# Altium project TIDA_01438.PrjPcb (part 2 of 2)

## Sheet TIDA_01438_TID_ADS1262.SchDoc
size 431 x 279 mm; Date: Not shown in title block; ApprovedBy: Not shown in title block; CheckedBy: Not shown in title block; Author: Not shown in title block; CompanyName: Not shown in title block; Engineer: Not shown in title block; Organization: Not shown in title block; Address1: Not shown in title block; Address2: Not shown in title block; Address3: Not shown in title block; Address4: Not shown in title block; DocumentNumber: 1; Revision: Use project parameter SCH_Rev; SheetNumber: 2; SheetTotal: 3; PageSetup: Record=PageOptions¦CenterHorizontal=True¦CenterVertical=True¦PrintScale=0.62¦XCorrection=1.00¦YCorrection=1.00¦PrintKind=0¦BorderSize=5000000¦LeftOffset=0¦BottomOffset=0¦Orientation=2¦PaperLength=1000¦PaperWidth=1000¦Scale=100¦PaperSource=15¦PrintQuality=-3¦MediaType=1¦DitherType=10¦PrintScaleMode=1¦PaperKind=11x17¦PaperIndex=3
Used 2 times, as channels CH1/ADC, CH2/ADC. Parts and nets are listed once, with the designators drawn on the sheet.
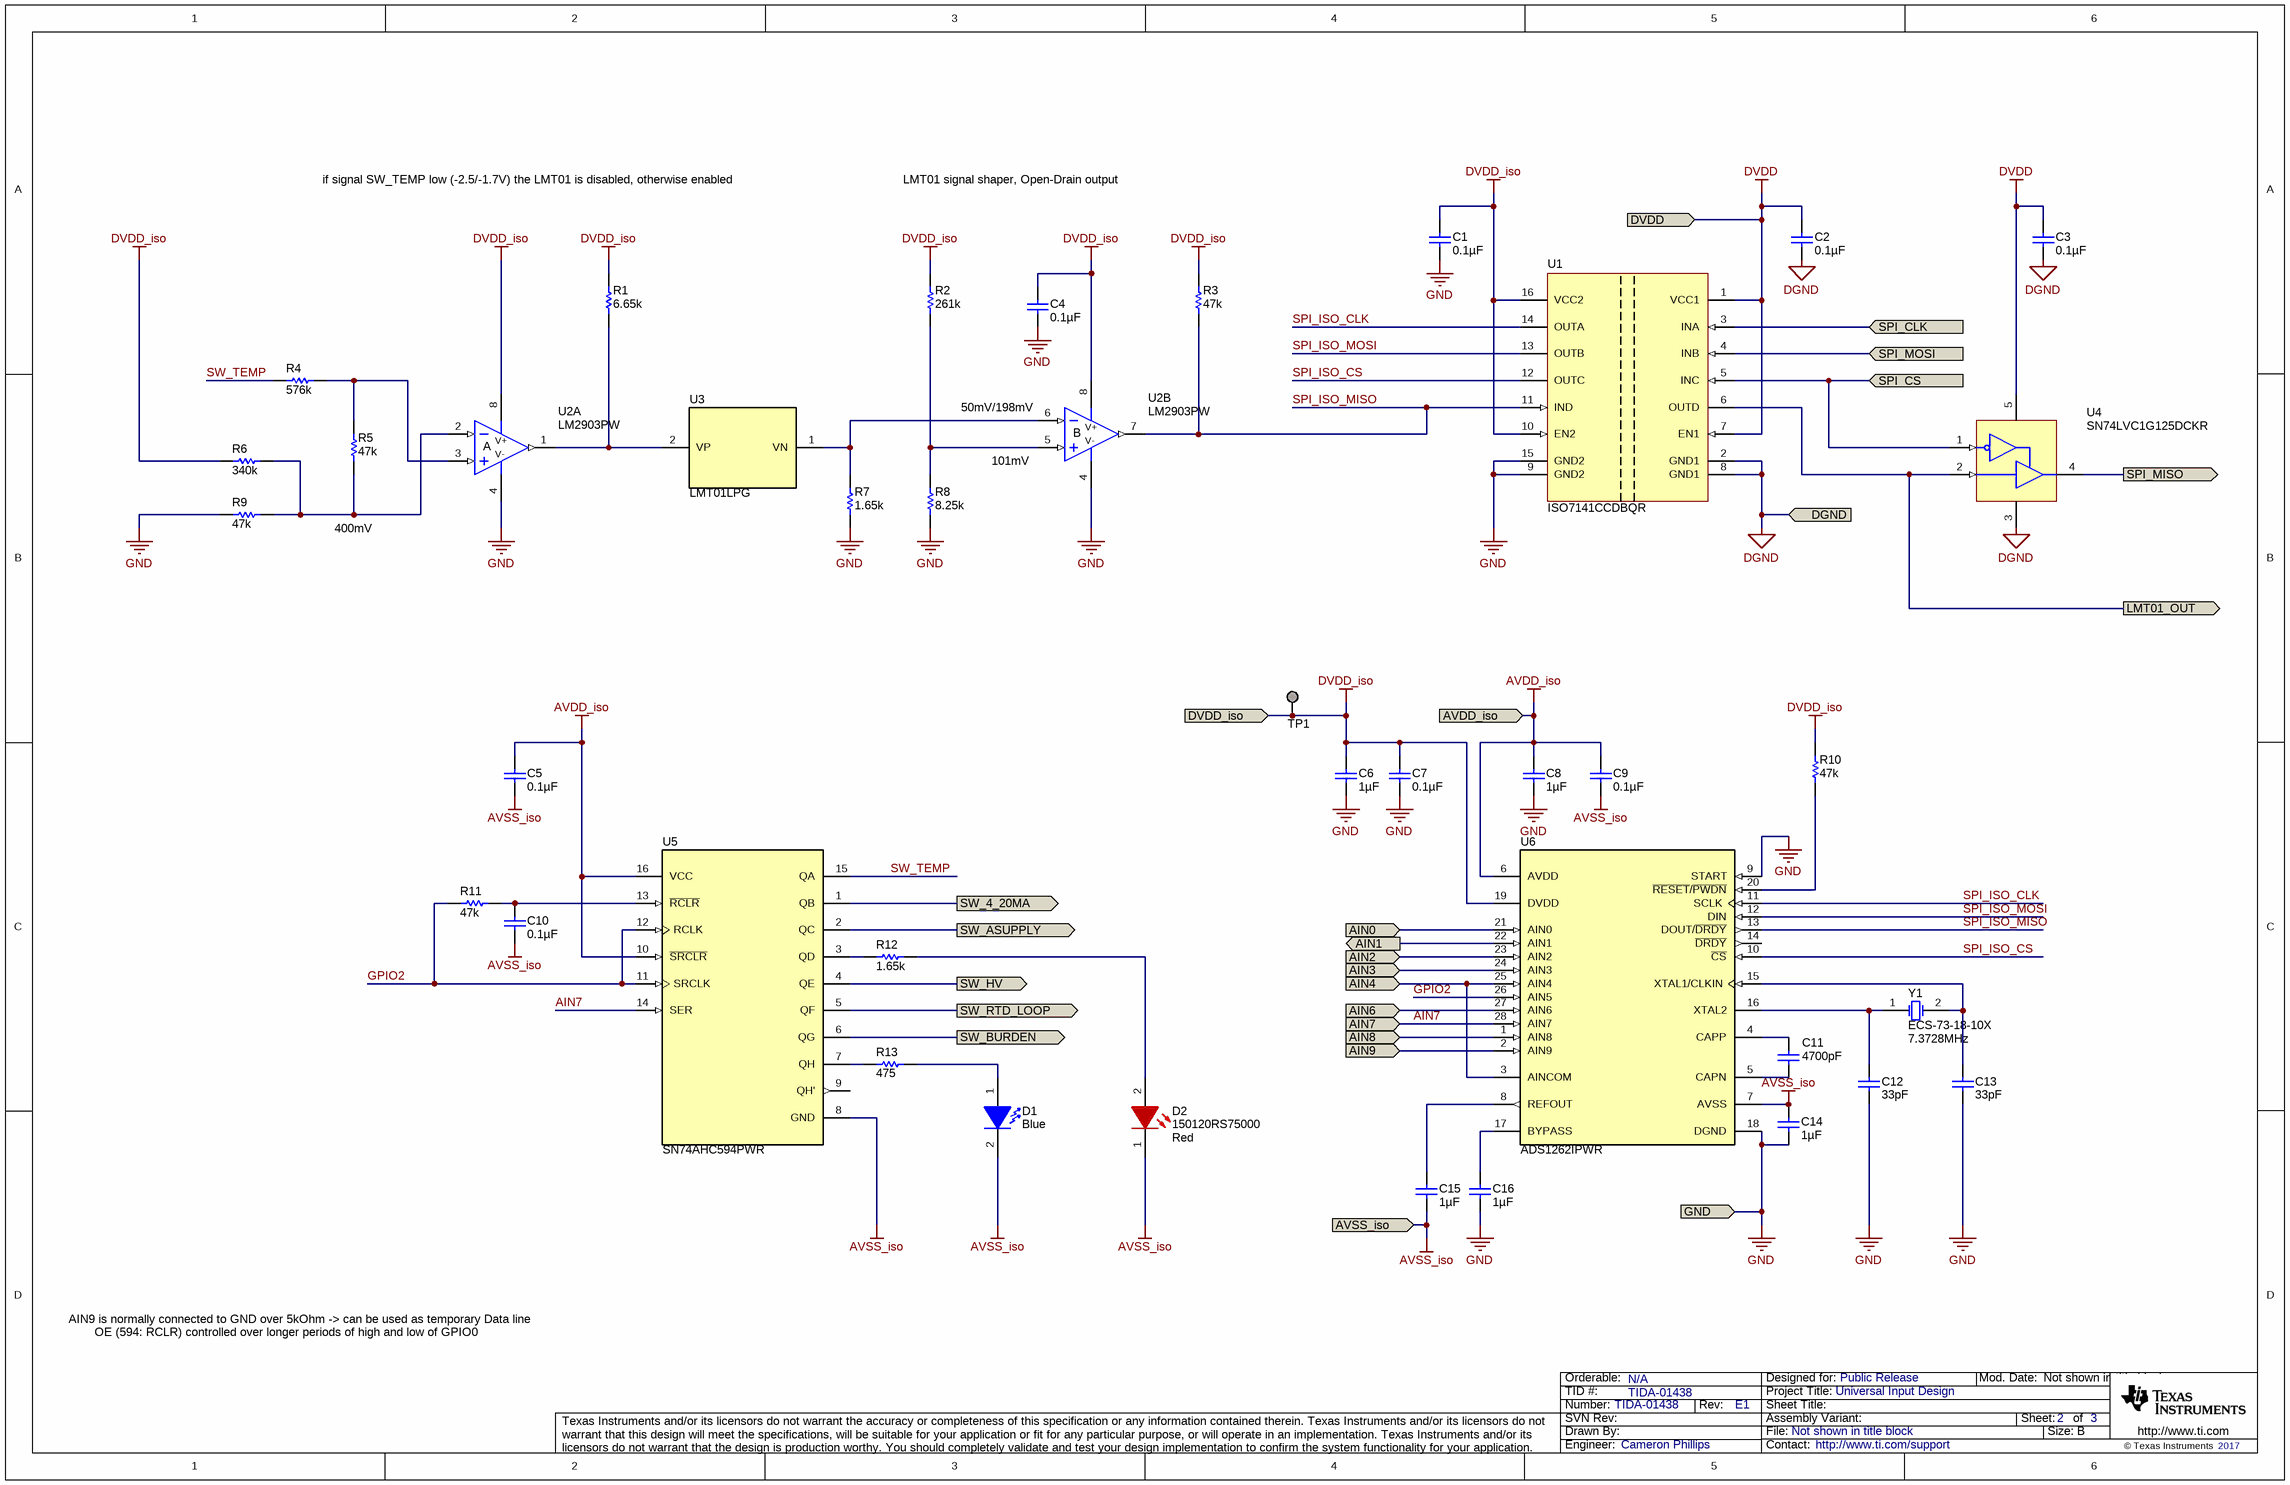
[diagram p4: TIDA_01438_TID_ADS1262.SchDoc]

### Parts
C1  ValueDisplayed: 0.1µF  [0402]  (hidden comment: C1005X7R1H104K)
C2  ValueDisplayed: 0.1µF  [0402]  (hidden comment: C1005X7R1H104K)
C3  ValueDisplayed: 0.1µF  [0402]  (hidden comment: C1005X7R1H104K)
C4  ValueDisplayed: 0.1µF  [0402]  (hidden comment: C1005X7R1H104K)
C5  ValueDisplayed: 0.1µF  [0402]  (hidden comment: C1005X7R1H104K)
C6  ValueDisplayed: 1µF  [0603]  (hidden comment: C1608X7R1C105K)
C7  ValueDisplayed: 0.1µF  [0402]  (hidden comment: C1005X7R1H104K)
C8  ValueDisplayed: 1µF  [0603]  (hidden comment: C1608X7R1C105K)
C9  ValueDisplayed: 0.1µF  [0402]  (hidden comment: C1005X7R1H104K)
C10  ValueDisplayed: 0.1µF  [0402]  (hidden comment: C1005X7R1H104K)
C11  ValueDisplayed: 4700pF  [0603]  (hidden comment: C1608C0G1E472J)
C12  ValueDisplayed: 33pF  [0402]  (hidden comment: GRM1555C1E330JA01D)
C13  ValueDisplayed: 33pF  [0402]  (hidden comment: GRM1555C1E330JA01D)
C14  ValueDisplayed: 1µF  [0603]  (hidden comment: C1608X7R1C105K)
C15  ValueDisplayed: 1µF  [0603]  (hidden comment: C1608X7R1C105K)
C16  ValueDisplayed: 1µF  [0603]  (hidden comment: C1608X7R1C105K)
D1  value Blue  [LB Q39G_BLUE]  (hidden comment: LB Q39G-L2N2-35-1)
D2  150120RS75000  value Red  [WL_SMCW_RED_1206]
R1  ValueDisplayed: 6.65k  [0402]  (hidden comment: CRCW04026K65FKED)
R2  ValueDisplayed: 261k  [0402]  (hidden comment: CRCW0402261KFKED)
R3  ValueDisplayed: 47k  [0402]  (hidden comment: CRCW040247K0JNED)
R4  ValueDisplayed: 576k  [0402]  (hidden comment: CRCW0402576KFKED)
R5  ValueDisplayed: 47k  [0402]  (hidden comment: CRCW040247K0JNED)
R6  ValueDisplayed: 340k  [0402]  (hidden comment: CRCW0402340KFKED)
R7  ValueDisplayed: 1.65k  [0402]  (hidden comment: CRCW04021K65FKED)
R8  ValueDisplayed: 8.25k  [0402]  (hidden comment: CRCW04028K25FKED)
R9  ValueDisplayed: 47k  [0402]  (hidden comment: CRCW040247K0JNED)
R10  ValueDisplayed: 47k  [0402]  (hidden comment: CRCW040247K0JNED)
R11  ValueDisplayed: 47k  [0402]  (hidden comment: CRCW040247K0JNED)
R12  ValueDisplayed: 1.65k  [0402]  (hidden comment: CRCW04021K65FKED)
R13  ValueDisplayed: 475  [0402]  (hidden comment: CRCW0402475RFKED)
TP1  TESTPOINT  [TESTPOINT]  (value not drawn)  (no BOM)
U1  ISO7141CCDBQR  [DBQ0016A_N]
U2  LM2903PW  [PW0008A_N]  (parts A,B of 2)
U3  LMT01LPG  [LPG0002A]
U4  SN74LVC1G125DCKR  [DCK0005A_N]
U5  SN74AHC594PWR  [PW0016A_N]
U6  ADS1262IPWR  [PW0028A_N]
Y1  ECS-73-18-10X  Frequency: 7.3728MHz  [ECS-3x10X]

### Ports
AIN0 (in), AIN1 (out), AIN2 (in), AIN3 (in), AIN4 (in), AIN6 (in), AIN7 (in), AIN8 (in), AIN9 (in), AVDD_iso (in), AVSS_iso (in), DGND (in), DVDD (in), DVDD_iso (in), GND (in), LMT01_OUT (out), SPI_CLK (in), SPI_CS (in), SPI_MISO (out), SPI_MOSI (in), SW_4_20MA (out), SW_ASUPPLY (out), SW_BURDEN (out), SW_HV (out), SW_RTD_LOOP (out)

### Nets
AVDD_iso: C5.1 C8.1 C9.1 U5.10(~{SRCLR}) U5.16(VCC) U6.6(AVDD) ; port AVDD_iso
AVSS_iso: C5.2 C9.2 C10.2 C14.1 C15.2 D1.2(K) D2.1(K) U5.8(GND) U6.7(AVSS) ; port AVSS_iso
DGND: C2.2 C3.2 U1.2(GND1) U1.8(GND1) U4.3(GND) ; port DGND
DVDD: C2.1 C3.1 U1.1(VCC1) U1.7(EN1) U4.5(VCC) ; port DVDD
DVDD_iso: C1.1 C4.1 C6.1 C7.1 R1.1 R2.1 R3.1 R6.2 R10.1 TP1.1 U1.10(EN2) U1.16(VCC2) U2.8(V+) U6.19(DVDD) ; port DVDD_iso
GND: C1.2 C4.2 C6.2 C7.2 C8.2 C12.2 C13.2 C14.2 C16.2 R7.1 R8.2 R9.1 U1.9(GND2) U1.15(GND2) U2.4(V-) U6.9(START) U6.18(DGND) ; port GND
AIN0: U6.21(AIN0) ; port AIN0
AIN1: U6.22(AIN1) ; port AIN1
AIN2: U6.23(AIN2) ; port AIN2
AIN3: U6.24(AIN3) ; port AIN3
AIN4: U6.3(AINCOM) U6.25(AIN4) ; port AIN4
AIN6: U6.27(AIN6) ; port AIN6
AIN7: U5.14(SER) U6.28(AIN7) ; port AIN7
AIN8: U6.1(AIN8) ; port AIN8
AIN9: U6.2(AIN9) ; port AIN9
GPIO2: R11.1 U5.11(SRCLK) U5.12(RCLK) U6.26(AIN5)
LMT01_OUT: U1.6(OUTD) U4.2(A) ; port LMT01_OUT
SPI_CLK: U1.3(INA) ; port SPI_CLK
SPI_CS: U1.5(INC) U4.1(~{OE}) ; port SPI_CS
SPI_ISO_CLK: U1.14(OUTA) U6.11(SCLK)
SPI_ISO_CS: U1.12(OUTC) U6.10(~{CS})
SPI_ISO_MISO: R3.2 U1.11(IND) U2.7(OUT) U6.13(DOUT/~{DRDY})
SPI_ISO_MOSI: U1.13(OUTB) U6.12(DIN)
SPI_MISO: U4.4(Y) ; port SPI_MISO
SPI_MOSI: U1.4(INB) ; port SPI_MOSI
SW_4_20MA: U5.1(QB) ; port SW_4_20MA
SW_ASUPPLY: U5.2(QC) ; port SW_ASUPPLY
SW_BURDEN: U5.6(QG) ; port SW_BURDEN
SW_HV: U5.4(QE) ; port SW_HV
SW_RTD_LOOP: U5.5(QF) ; port SW_RTD_LOOP
SW_TEMP: R4.2 U5.15(QA)
NetC10_1: C10.1 R11.2 U5.13(~{RCLR})
NetC11_1: C11.1 U6.4(CAPP)
NetC11_2: C11.2 U6.5(CAPN)
NetC12_1: C12.1 U6.16(XTAL2) Y1.1(OSC1)
NetC13_1: C13.1 U6.15(XTAL1/CLKIN) Y1.2(OSC2)
NetC15_1: C15.1 U6.8(REFOUT)
NetC16_1: C16.1 U6.17(BYPASS)
NetD1_1: D1.1(A) R13.2
NetD2_2: D2.2(A) R12.2
NetR1_2: R1.2 U2.1(OUT) U3.2(VP)
NetR2_2: R2.2 R8.1 U2.5(IN+)
NetR4_1: R4.1 R5.1 U2.3(IN+)
NetR5_2: R5.2 R6.1 R9.2 U2.2(IN-)
NetR7_2: R7.2 U2.6(IN-) U3.1(VN)
NetR10_2: R10.2 U6.20(~{RESET}/~{PWDN})
NetR12_1: R12.1 U5.3(QD)
NetR13_1: R13.1 U5.7(QH)

Not connected (* = marked no-connect by the designer): U5 9(QH'); U6 14(~{DRDY})

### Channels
CH1/ADC: designators end in _ADC1; ports AIN0=AIN0 AIN1=AIN1 AIN2=AIN2 AIN3=AIN3 AIN4=AIN4 AIN6=AIN6 AIN7=AIN7 AIN8=AIN8 AIN9=AIN9 AVDD_iso=AVDD_iso AVSS_iso=AVSS_iso DGND=DGND DVDD=DVDD DVDD_iso=DVDD_iso GND=GND LMT01_OUT=LMT01_OUT1 SPI_CLK=SPI_CLK SPI_CS=SPI_CS1 SPI_MISO=SPI_MISO SPI_MOSI=SPI_MOSI SW_4_20MA=SW_4_20MA SW_ASUPPLY=SW_ASUPPLY SW_BURDEN=SW_BURDEN SW_HV=SW_HV SW_RTD_LOOP=SW_RTD_LOOP
CH2/ADC: designators end in _ADC2; ports AIN0=AIN0 AIN1=AIN1 AIN2=AIN2 AIN3=AIN3 AIN4=AIN4 AIN6=AIN6 AIN7=AIN7 AIN8=AIN8 AIN9=AIN9 AVDD_iso=AVDD_iso AVSS_iso=AVSS_iso DGND=DGND DVDD=DVDD DVDD_iso=DVDD_iso GND=GND LMT01_OUT=LMT01_OUT2 SPI_CLK=SPI_CLK SPI_CS=SPI_CS2 SPI_MISO=SPI_MISO SPI_MOSI=SPI_MOSI SW_4_20MA=SW_4_20MA SW_ASUPPLY=SW_ASUPPLY SW_BURDEN=SW_BURDEN SW_HV=SW_HV SW_RTD_LOOP=SW_RTD_LOOP

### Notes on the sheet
- if signal SW_TEMP low (-2.5/-1.7V) the LMT01 is disabled, otherwise enabled
- LMT01 signal shaper, Open-Drain output
- (near U2) 50mV/198mV
- (near U2) 101mV
- 400mV
- OE (594: RCLR) controlled over longer periods of high and low of GPIO0
- AIN9 is normally connected to GND over 5kOhm -> can be used as temporary Data line

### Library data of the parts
C1-C5 C7 C9 C10 = C1005X7R1H104K: CAP, CERM, 0.1 µF, 50 V, +/- 10%, X7R, 0402; Manufacturer: TDK; Polarized: N; CompType: Capacitor; Value: 0.1uF; U/M: EA; Cap_F: 0.0000001; Tolerance_%: 10; Value1: Unknown; VDC_V: 50; Value2: 50V; TaMin_C: -55; TaMax_C: 125; AEC Category: Q200
C6 C8 C15 C16 = C1608X7R1C105K: CAP, CERM, 1 µF, 16 V, +/- 10%, X7R, 0603; Manufacturer: TDK; Polarized: N; CompType: Capacitor; Value: 1uF; U/M: EA; Cap_F: 0.000001; Tolerance_%: 10; ESR_ohm: 0.0057; Value1: 0.0057 ohm; VDC_V: 16; Value2: 16V; TaMin_C: -55; TaMax_C: 125
C11 = C1608C0G1E472J: CAP, CERM, 4700 pF, 25 V, +/- 5%, C0G/NP0, 0603; Manufacturer: TDK; Polarized: N; CompType: Capacitor; Value: 4700pF; U/M: EA; Cap_F: 0.0000000047; Tolerance_%: 5; Value1: Unknown; VDC_V: 25; Value2: 25V; TaMin_C: -55; TaMax_C: 125
C12 C13 = GRM1555C1E330JA01D: CAP, CERM, 33 pF, 25 V, +/- 5%, C0G/NP0, 0402; Manufacturer: MuRata; Polarized: N; CompType: Capacitor; Value: 33pF; U/M: EA; Cap_F: 0.000000000033; Tolerance_%: 5; Value1: Unknown; VDC_V: 25; Value2: 25V; TaMin_C: -55; TaMax_C: 125; AEC Category: Q200
C14 = C1608X7R1C105K: CAP, CERM, 1 µF, 16 V, +/- 10%, X7R, 0603; Manufacturer: TDK; Polarized: N; CompType: Capacitor; Value: 1uF; U/M: EA; Cap_F: 0.000001; Tolerance_%: 10; ESR_ohm: 0.0057; Value1: 0.0057 ohm; VDC_V: 16; Value2: 16V; TaMin_C: -55; TaMax_C: 125; AEC Category: Q200
D1 = LB Q39G-L2N2-35-1: LED, Blue, SMD; Manufacturer: OSRAM; Vf_V: 2.85; Value2: 2.85V; Io_A: 0.15; Tjmax_C: 95; Value1: W; U/M: EA
D2 = 150120RS75000: LED, Red, SMD; Manufacturer: Wurth Elektronik; SymbolCreator: Altium; Type: AlInGaP; Vf_V: 2; Value2: 2V; Io_A: 0.02; Vr_V: 5; Ir_A: 1e-005; Tjmax_C: 85; Power_TotalModule: 0.072; Value1: 0.072W; Angle: 140; U/M: EA
R1 = CRCW04026K65FKED: RES, 6.65 k, 1%, 0.063 W, 0402; Manufacturer: Vishay-Dale; CompType: Resistor; Value: 6.65k; Res_ohm: 6650; Value_Code: 6k65; Tolerance_%: 1; Power_W: 0.063; Value2: 0.063W; VDC_V: 50; TempCo: 100 ppm/C; EIA_Code: E96; U/M: EA; AEC Category: Q200
R2 = CRCW0402261KFKED: RES, 261 k, 1%, 0.063 W, 0402; Manufacturer: Vishay-Dale; CompType: Resistor; Value: 261k; Res_ohm: 261000; Tolerance_%: 1; Power_W: 0.063; Value2: 0.063W; VDC_V: 50; TempCo: 100 ppm/C; EIA_Code: E96; U/M: EA; AEC Category: Q200
R3 R5 R9-R11 = CRCW040247K0JNED: RES, 47 k, 5%, 0.063 W, 0402; Manufacturer: Vishay-Dale; CompType: Resistor; Value: 47k; Res_ohm: 47000; Value_Code: 47k0; Tolerance_%: 5; Power_W: 0.063; Value2: 0.063W; VDC_V: 50; TempCo: 200 ppm/C; EIA_Code: E24; U/M: EA; AEC Category: Q200
R4 = CRCW0402576KFKED: RES, 576 k, 1%, 0.063 W, 0402; Manufacturer: Vishay-Dale; CompType: Resistor; Value: 576k; Res_ohm: 576000; Tolerance_%: 1; Power_W: 0.063; Value2: 0.063W; VDC_V: 50; TempCo: 100 ppm/C; EIA_Code: E96; U/M: EA; AEC Category: Q200
R6 = CRCW0402340KFKED: RES, 340 k, 1%, 0.063 W, 0402; Manufacturer: Vishay-Dale; CompType: Resistor; Value: 340k; Res_ohm: 340000; Tolerance_%: 1; Power_W: 0.063; Value2: 0.063W; VDC_V: 50; TempCo: 100 ppm/C; EIA_Code: E96; U/M: EA; AEC Category: Q200
R7 R12 = CRCW04021K65FKED: RES, 1.65 k, 1%, 0.063 W, 0402; Manufacturer: Vishay-Dale; CompType: Resistor; Value: 1.65k; Res_ohm: 1650; Value_Code: 1k65; Tolerance_%: 1; Power_W: 0.063; Value2: 0.063W; VDC_V: 50; TempCo: 100 ppm/C; EIA_Code: E96; U/M: EA; AEC Category: Q200
R8 = CRCW04028K25FKED: RES, 8.25 k, 1%, 0.063 W, 0402; Manufacturer: Vishay-Dale; CompType: Resistor; Value: 8.25k; Res_ohm: 8250; Value_Code: 8k25; Tolerance_%: 1; Power_W: 0.063; Value2: 0.063W; VDC_V: 50; TempCo: 100 ppm/C; EIA_Code: E96; U/M: EA; AEC Category: Q200
R13 = CRCW0402475RFKED: RES, 475, 1%, 0.063 W, 0402; Manufacturer: Vishay-Dale; CompType: Resistor; Value: 475; Value_Code: 475R; Tolerance_%: 1; Power_W: 0.063; Value2: 0.063W; VDC_V: 50; TempCo: 100 ppm/C; EIA_Code: E96; U/M: EA; AEC Category: Q200
TP1 = TESTPOINT: TEST POINT.  No entry in BOM.
U1 = ISO7141CCDBQR: 4242-VPK Small-Footprint and Low-Power Quad Channels Digital Isolators, DBQ0016A; Manufacturer: Texas Instruments; SymbolCreator: a0799628; CompType: IC; U/M: EA
U2 = LM2903PW: Dual Comparator, PW0008A; Manufacturer: Texas Instruments; CompType: OpAmp IC
U3 = LMT01LPG: 0.5°C Accurate 2-Pin Digital NTC or PTC Thermistor Replacement, LPG0002A; Manufacturer: Texas Instruments; SymbolCreator: Altium; CompType: IC; U/M: EA
U4 = SN74LVC1G125DCKR: Single Bus Buffer Gate With 3-State Output, DCK0005A; Alternate PartNumber: SN74LVC1G125DCKT; Manufacturer: Texas Instruments; SymbolCreator: Altium; CompType: IC; U/M: EA
U5 = SN74AHC594PWR: 8-Bit Shift Register With Output Registers, PW0016A; Manufacturer: Texas Instruments; SymbolCreator: Altium; CompType: IC; U/M: EA
U6 = ADS1262IPWR: 32-Bit, Precision, 38-kSPS, Analog-to-Digital Converter (ADC) with Programmable Gain Amplifier (PGA) and Voltage Reference, PW0028A; Manufacturer: Texas Instruments; SymbolCreator: Altium; CompType: IC; U/M: EA
Y1 = ECS-73-18-10X: Crystal, 7.3728MHz, 18pF, SMD; Manufacturer: ECS Inc.; SymbolCreator: a0412235; U/M: EA; TaMin_C: -10; TaMax_C: 60; Frequency Stability: ±50ppm

## Sheet TIDA_01438_TID_HART.SchDoc
size 431 x 279 mm; Date: Not shown in title block; ApprovedBy: Not shown in title block; CheckedBy: Not shown in title block; Author: Not shown in title block; CompanyName: Not shown in title block; Engineer: Not shown in title block; Organization: Not shown in title block; Address1: Not shown in title block; Address2: Not shown in title block; Address3: Not shown in title block; Address4: Not shown in title block; DocumentNumber: 1; Revision: Use project parameter SCH_Rev; SheetNumber: 2; SheetTotal: 3; PageSetup: Record=PageOptions¦CenterHorizontal=True¦CenterVertical=True¦PrintScale=1.00¦XCorrection=1.00¦YCorrection=1.00¦PrintKind=0¦BorderSize=5000000¦LeftOffset=0¦BottomOffset=0¦Orientation=2¦PaperLength=1000¦PaperWidth=1000¦Scale=100¦PaperSource=15¦PrintQuality=600¦MediaType=1¦DitherType=10¦PaperKind=Letter¦PrintScaleMode=1
Used 2 times, as channels CH1/HART, CH2/HART. Parts and nets are listed once, with the designators drawn on the sheet.
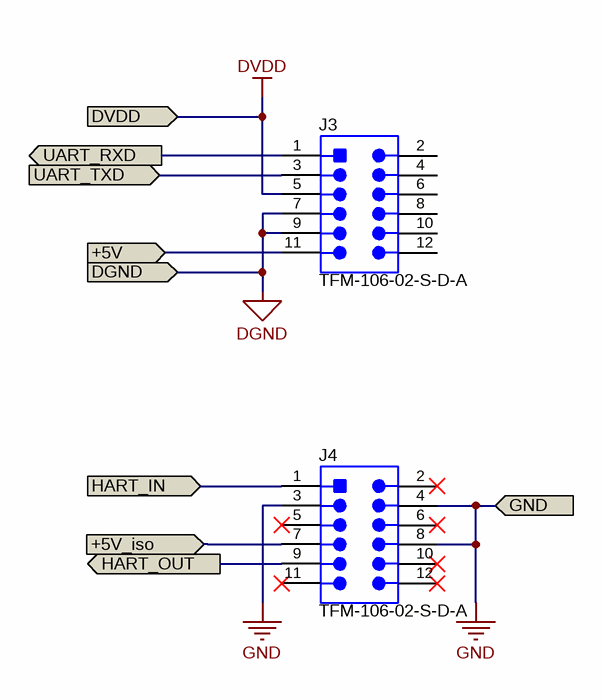
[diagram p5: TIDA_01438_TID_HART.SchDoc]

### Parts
J3  TFM-106-02-S-D-A  [Samtec_TFM-106-02-x-D-A]
J4  TFM-106-02-S-D-A  [Samtec_TFM-106-02-x-D-A]

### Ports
+5V (in), +5V_iso (in), DGND (in), DVDD (in), GND (in), HART_IN (in), HART_OUT (out), UART_RXD (out), UART_TXD (in)

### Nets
DGND: J3.7 J3.9 ; port DGND
DVDD: J3.5 ; port DVDD
GND: J4.3 J4.4 J4.8 ; port GND
+5V: J3.11 ; port +5V
+5V_iso: J4.7 ; port +5V_iso
HART_IN: J4.1 ; port HART_IN
HART_OUT: J4.9 ; port HART_OUT
UART_RXD: J3.1 ; port UART_RXD
UART_TXD: J3.3 ; port UART_TXD

Not connected (* = marked no-connect by the designer): J3 2 4 6 8 10 12; J4 2* 5* 6* 10* 11* 12*

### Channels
CH1/HART: designators end in _HART1; ports +5V=+5V +5V_iso=+5V_iso DGND=DGND DVDD=DVDD GND=GND HART_IN=HART_IN HART_OUT=HART_OUT UART_RXD=UART_RXD1 UART_TXD=UART_TXD1
CH2/HART: designators end in _HART2; ports +5V=+5V +5V_iso=+5V_iso DGND=DGND DVDD=DVDD GND=GND HART_IN=HART_IN HART_OUT=HART_OUT UART_RXD=UART_RXD2 UART_TXD=UART_TXD2

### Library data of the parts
J3 J4 = TFM-106-02-S-D-A: Header(Shrouded), 1.27mm, 6x2, Tin, SMT; Manufacturer: Samtec; SymbolCreator: a0412235; U/M: EA

## Sheet TIDA_01438_CoverSheet.SchDoc: Block Diagram
size 431 x 279 mm; Date: Not shown in title block; ApprovedBy: Not shown in title block; CheckedBy: Not shown in title block; Author: Not shown in title block; CompanyName: Not shown in title block; DrawnBy: Lars Lotzenburger; Engineer: Not shown in title block; Organization: Not shown in title block; Address1: Not shown in title block; Address2: Not shown in title block; Address3: Not shown in title block; Address4: Not shown in title block; DocumentNumber: 1; Revision: Use project parameter SCH_Rev; SheetNumber: 1; SheetTotal: 3; PageSetup: Record=PageOptions¦CenterHorizontal=True¦CenterVertical=True¦PrintScale=1.00¦XCorrection=1.00¦YCorrection=1.00¦PrintKind=0¦BorderSize=5000000¦LeftOffset=0¦BottomOffset=0¦Orientation=2¦PaperLength=1000¦PaperWidth=1000¦Scale=100¦PaperSource=15¦PrintQuality=600¦MediaType=1¦DitherType=10¦PaperKind=Letter¦PrintScaleMode=1
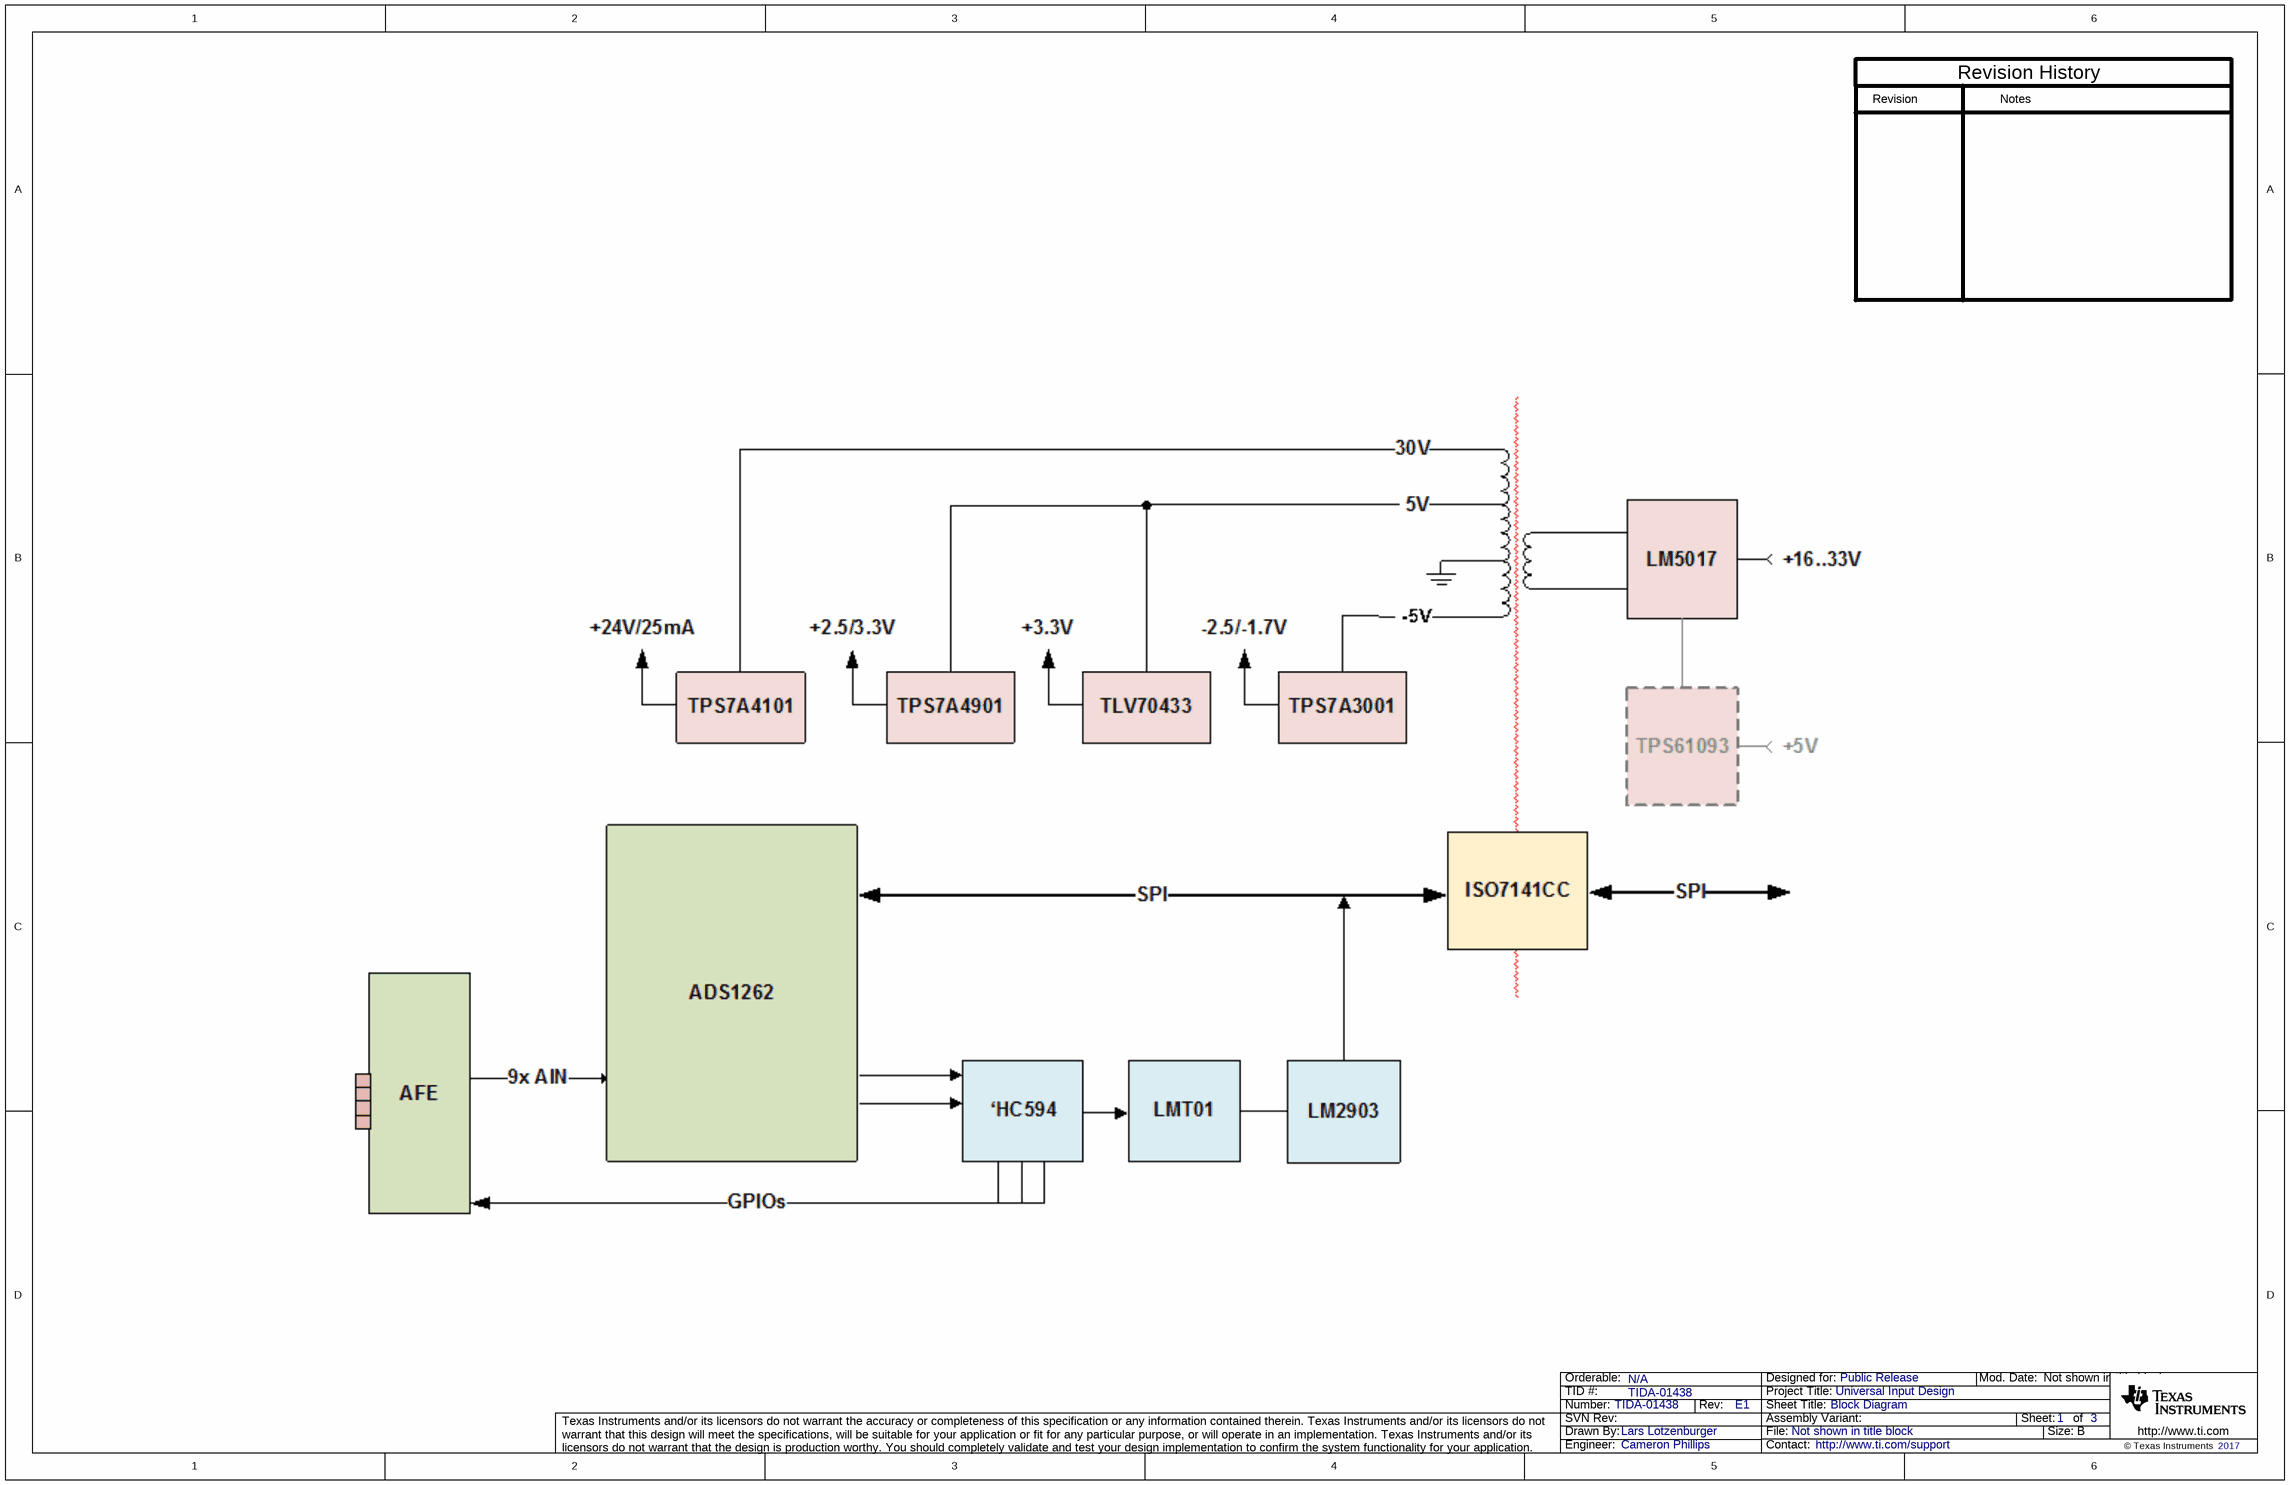
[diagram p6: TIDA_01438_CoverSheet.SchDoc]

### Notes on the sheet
- Revision
- Notes
- Revision History

## Sheet TIDA_01438_TID_Hardware.SchDoc: Hardware
size 431 x 279 mm; Date: Not shown in title block; ApprovedBy: Not shown in title block; CheckedBy: Not shown in title block; Author: Not shown in title block; CompanyName: Not shown in title block; DrawnBy: Lars Lotzenburger; Engineer: Not shown in title block; Organization: Not shown in title block; Address1: Not shown in title block; Address2: Not shown in title block; Address3: Not shown in title block; Address4: Not shown in title block; DocumentNumber: 3; Revision: Use project parameter SCH_Rev; SheetNumber: 3; SheetTotal: 3; PageSetup: Record=PageOptions¦CenterHorizontal=True¦CenterVertical=True¦PrintScale=1.00¦XCorrection=1.00¦YCorrection=1.00¦PrintKind=0¦BorderSize=5000000¦LeftOffset=0¦BottomOffset=0¦Orientation=2¦PaperLength=1000¦PaperWidth=1000¦Scale=100¦PaperSource=15¦PrintQuality=600¦MediaType=1¦DitherType=10¦PaperKind=Letter¦PrintScaleMode=1
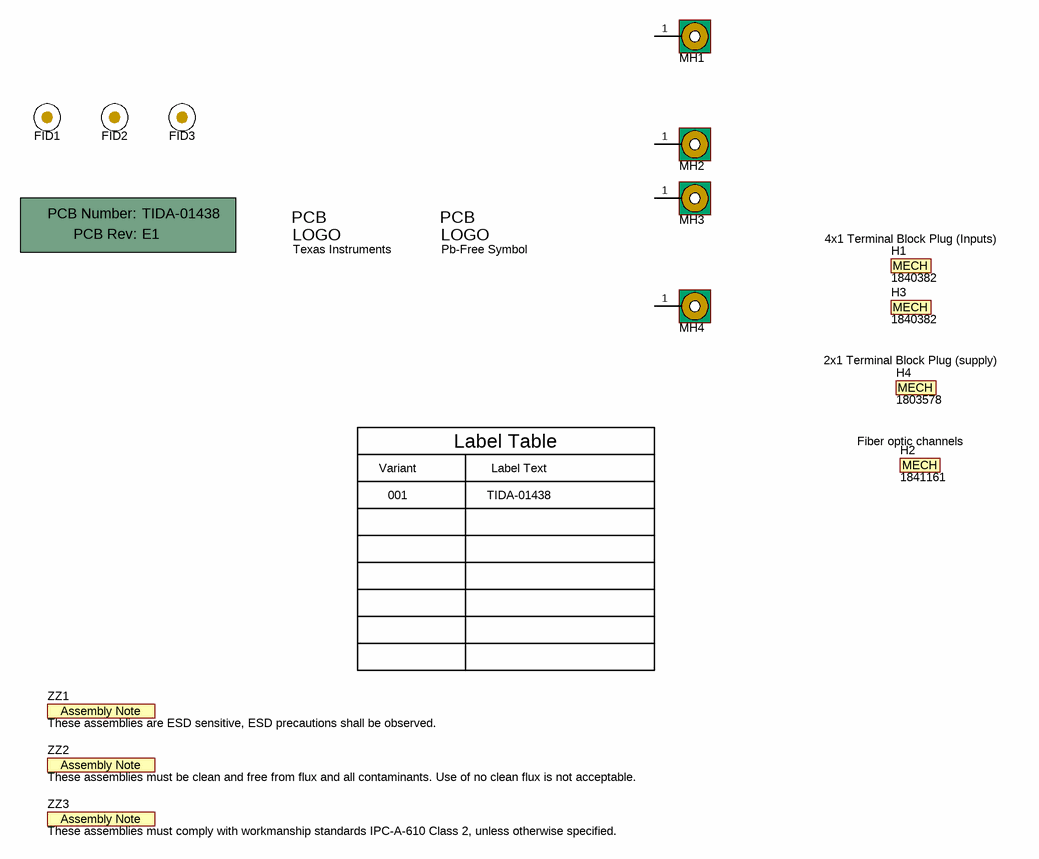
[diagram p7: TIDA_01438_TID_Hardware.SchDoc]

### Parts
!PCB1  Printed Circuit Board  (value not drawn)  (mechanical)
FID1  Fiducial  [Fiducial10-20]  (value not drawn)
FID2  Fiducial  [Fiducial10-20]  (value not drawn)
FID3  Fiducial  [Fiducial10-20]  (value not drawn)
H1  1840382  (mechanical)
H2  1841161  (mechanical)
H3  1840382  (mechanical)
H4  1803578  (mechanical)
Logo1  Texas Instruments  [TI_Stacked_SolderMask_Small]  (no BOM)
Logo2  Pb-Free Symbol  [Pb-Free_Overlay_Small]  (no BOM)
MH1  MTG_Pads  [MTGP_4-40_PanHead]  (value not drawn)  (no BOM)
MH2  MTG_Pads  [MTGP_4-40_PanHead]  (value not drawn)  (no BOM)
MH3  MTG_Pads  [MTGP_4-40_PanHead]  (value not drawn)  (no BOM)
MH4  MTG_Pads  [MTGP_4-40_PanHead]  (value not drawn)  (no BOM)
ZZ1  These assemblies are ESD sensitive, ESD precautions shall be observed.  [AssemblyNote]  (no BOM)
ZZ2  These assemblies must be clean and free from flux and all contaminants. Use of no clean flux is not acceptable.  [AssemblyNote]  (no BOM)
ZZ3  These assemblies must comply with workmanship standards IPC-A-610 Class 2, unless otherwise specified.  [AssemblyNote]  (no BOM)

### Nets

Not connected (* = marked no-connect by the designer): MH1 1; MH2 1; MH3 1; MH4 1

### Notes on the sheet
- (near H1) 4x1 Terminal Block Plug (Inputs)
- (near H4) 2x1 Terminal Block Plug (supply)
- Variant
- Label Table
- Label Text
- (near H2) Fiber optic channels
- 001
- TIDA-01438

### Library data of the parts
!PCB1 = PCB: Manufacturer: Any; PartNumber: TIDA-01438; SymbolCreator: a0412235
FID1-FID3 = Fiducial: Fiducial mark.  There is nothing to buy or mount.; SymbolCreator: codlsc
H1 H3 = 1840382: Terminal Block Plug, 3.5mm, 4x1, Green; Manufacturer: Phoenix Contact; SymbolCreator: codlsc; CompType: TERM BLOCK
H2 = 1841161: Fiber optics - MC 1,5/10-LWL 1,5-3,5 for Phoenix connectors; Manufacturer: Phoenix Contact; SymbolCreator: codlsc; CompType: Filber Optics
H4 = 1803578: Terminal Block Plug, 3.81mm, 2x1, Green; Manufacturer: Phoenix Contact; SymbolCreator: codlsc; CompType: TERM BLOCK
Logo1 = TI_Logo: Texas Instrument Corporate Signature; SymbolCreator: codlsc
Logo2 = Pb-Free: SymbolCreator: a0412235
MH1-MH4 = Mounting Hole (Imperial) with Pads: PCB Mounting Hole; Manufacturer: Any; SymbolCreator: a0412235
ZZ1-ZZ3 = AssemblyNote: SymbolCreator: codlsc

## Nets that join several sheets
AVDD_iso: CH1/PWR (5 pins), CH1/ADC (6 pins)
AVDD_iso: CH2/PWR (5 pins), CH2/ADC (6 pins)
AVSS_iso: CH1/AFE (D3_AFE1.2 D6_AFE1.2 D8_AFE1.2), CH1/PWR (9 pins), CH1/ADC (9 pins)
AVSS_iso: CH2/AFE (D3_AFE2.2 D6_AFE2.2 D8_AFE2.2), CH2/PWR (9 pins), CH2/ADC (9 pins)
DGND: TIDA_01438_TID_Cape (33 pins), CH1/PWR (10 pins), CH1/ADC (5 pins), CH1/HART (J3_HART1.7 J3_HART1.9), CH2/PWR (10 pins), CH2/ADC (5 pins), CH2/HART (J3_HART2.7 J3_HART2.9)
DVDD: TIDA_01438_TID_Cape (20 pins), CH1/ADC (5 pins), CH1/HART (J3_HART1.5), CH2/ADC (5 pins), CH2/HART (J3_HART2.5)
DVDD_iso: CH1/PWR (C44_PWR1.1 D14_PWR1.2 D15_PWR1.1 U13_PWR1.3), CH1/ADC (14 pins)
DVDD_iso: CH2/PWR (C44_PWR2.1 D14_PWR2.2 D15_PWR2.1 U13_PWR2.3), CH2/ADC (14 pins)
GND: CH1/AFE (22 pins), CH1/PWR (32 pins), CH1/ADC (17 pins), CH1/HART (J4_HART1.3 J4_HART1.4 J4_HART1.8)
GND: CH2/AFE (22 pins), CH2/PWR (32 pins), CH2/ADC (17 pins), CH2/HART (J4_HART2.3 J4_HART2.4 J4_HART2.8)
4-20mA LOOP: CH1/AFE (D4_AFE1.3), CH1/PWR (R46_PWR1.1 R49_PWR1.2)
4-20mA LOOP: CH2/AFE (D4_AFE2.3), CH2/PWR (R46_PWR2.1 R49_PWR2.2)
+5V: TIDA_01438_TID_Cape (7 pins), CH1/HART (J3_HART1.11), CH2/HART (J3_HART2.11)
+5V_iso: CH1/PWR (6 pins), CH1/HART (J4_HART1.7)
+5V_iso: CH2/PWR (6 pins), CH2/HART (J4_HART2.7)
AIN0: CH1/AFE (C21_AFE1.1 R18_AFE1.2 R19_AFE1.2), CH1/ADC (U6_ADC1.21)
AIN0: CH2/AFE (C21_AFE2.1 R18_AFE2.2 R19_AFE2.2), CH2/ADC (U6_ADC2.21)
AIN1: CH1/AFE (R14_AFE1.1 R16_AFE1.2), CH1/ADC (U6_ADC1.22)
AIN1: CH2/AFE (R14_AFE2.1 R16_AFE2.2), CH2/ADC (U6_ADC2.22)
AIN2: CH1/AFE (C17_AFE1.1 C18_AFE1.1 R14_AFE1.2), CH1/ADC (U6_ADC1.23)
AIN2: CH2/AFE (C17_AFE2.1 C18_AFE2.1 R14_AFE2.2), CH2/ADC (U6_ADC2.23)
AIN3: CH1/AFE (C18_AFE1.2 C19_AFE1.2 R17_AFE1.2), CH1/ADC (U6_ADC1.24)
AIN3: CH2/AFE (C18_AFE2.2 C19_AFE2.2 R17_AFE2.2), CH2/ADC (U6_ADC2.24)
AIN4: CH1/AFE (C22_AFE1.1 C24_AFE1.1 R21_AFE1.2), CH1/ADC (U6_ADC1.3 U6_ADC1.25)
AIN4: CH2/AFE (C22_AFE2.1 C24_AFE2.1 R21_AFE2.2), CH2/ADC (U6_ADC2.3 U6_ADC2.25)
AIN6: CH1/AFE (C24_AFE1.2 C25_AFE1.2 R22_AFE1.2), CH1/ADC (U6_ADC1.27)
AIN6: CH2/AFE (C24_AFE2.2 C25_AFE2.2 R22_AFE2.2), CH2/ADC (U6_ADC2.27)
AIN7: CH1/AFE (R27_AFE1.2), CH1/ADC (U5_ADC1.14 U6_ADC1.28)
AIN7: CH2/AFE (R27_AFE2.2), CH2/ADC (U5_ADC2.14 U6_ADC2.28)
AIN8: CH1/AFE (C28_AFE1.1 C29_AFE1.1 R24_AFE1.2), CH1/ADC (U6_ADC1.1)
AIN8: CH2/AFE (C28_AFE2.1 C29_AFE2.1 R24_AFE2.2), CH2/ADC (U6_ADC2.1)
AIN9: CH1/AFE (C29_AFE1.2 C30_AFE1.2 R26_AFE1.2), CH1/ADC (U6_ADC1.2)
AIN9: CH2/AFE (C29_AFE2.2 C30_AFE2.2 R26_AFE2.2), CH2/ADC (U6_ADC2.2)
HART_IN: CH1/AFE (C26_AFE1.2), CH1/HART (J4_HART1.1)
HART_IN: CH2/AFE (C26_AFE2.2), CH2/HART (J4_HART2.1)
HART_OUT: CH1/PWR (C42_PWR1.2), CH1/HART (J4_HART1.9)
HART_OUT: CH2/PWR (C42_PWR2.2), CH2/HART (J4_HART2.9)
LMT01_OUT1: TIDA_01438_TID_Cape (J9.25), CH1/ADC (U1_ADC1.6 U4_ADC1.2)
LMT01_OUT2: TIDA_01438_TID_Cape (J9.27), CH2/ADC (U1_ADC2.6 U4_ADC2.2)
SPI_CLK: TIDA_01438_TID_Cape (J9.31), CH1/ADC (U1_ADC1.3), CH2/ADC (U1_ADC2.3)
SPI_CS1: TIDA_01438_TID_Cape (U8.4), CH1/ADC (U1_ADC1.5 U4_ADC1.1)
SPI_CS2: TIDA_01438_TID_Cape (U9.4), CH2/ADC (U1_ADC2.5 U4_ADC2.1)
SPI_MISO: TIDA_01438_TID_Cape (J9.29), CH1/ADC (U4_ADC1.4), CH2/ADC (U4_ADC2.4)
SPI_MOSI: TIDA_01438_TID_Cape (J9.30), CH1/ADC (U1_ADC1.4), CH2/ADC (U1_ADC2.4)
SW_4_20MA: CH1/PWR (Q3_PWR1.1 R51_PWR1.2), CH1/ADC (U5_ADC1.1)
SW_4_20MA: CH2/PWR (Q3_PWR2.1 R51_PWR2.2), CH2/ADC (U5_ADC2.1)
SW_ASUPPLY: CH1/PWR (Q4_PWR1.1 Q5_PWR1.1 R58_PWR1.1 R61_PWR1.1), CH1/ADC (U5_ADC1.2)
SW_ASUPPLY: CH2/PWR (Q4_PWR2.1 Q5_PWR2.1 R58_PWR2.1 R61_PWR2.1), CH2/ADC (U5_ADC2.2)
SW_BURDEN: CH1/AFE (R23_AFE1.1), CH1/ADC (U5_ADC1.6)
SW_BURDEN: CH2/AFE (R23_AFE2.1), CH2/ADC (U5_ADC2.6)
SW_HV: CH1/AFE (R20_AFE1.1), CH1/ADC (U5_ADC1.4)
SW_HV: CH2/AFE (R20_AFE2.1), CH2/ADC (U5_ADC2.4)
SW_RTD_LOOP: CH1/AFE (R15_AFE1.1), CH1/ADC (U5_ADC1.5)
SW_RTD_LOOP: CH2/AFE (R15_AFE2.1), CH2/ADC (U5_ADC2.5)
UART_RXD1: TIDA_01438_TID_Cape (J9.26), CH1/HART (J3_HART1.1)
UART_RXD2: TIDA_01438_TID_Cape (J9.22), CH2/HART (J3_HART2.1)
UART_TXD1: TIDA_01438_TID_Cape (J9.24), CH1/HART (J3_HART1.3)
UART_TXD2: TIDA_01438_TID_Cape (J9.21), CH2/HART (J3_HART2.3)
VIN: TIDA_01438_TID_Cape (D10.1 D11.2 D20.1 TP7.1), CH1/PWR (R62_PWR1.1), CH2/PWR (R62_PWR2.1)

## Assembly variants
001: not fitted FID1 FID2 FID3 R31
